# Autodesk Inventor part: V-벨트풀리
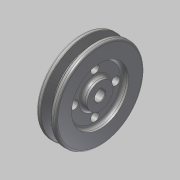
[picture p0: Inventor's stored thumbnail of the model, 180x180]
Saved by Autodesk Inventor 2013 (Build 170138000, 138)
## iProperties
Created: 2015-09
Part Number: V-벨트풀리
Material: 강철, 연강
Document SubType Name: Modeling
Designer: mduedu
Density: 1 g/cm^3
Author: mduedu
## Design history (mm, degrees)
sketch "스케치1"
  geometry: L1 (-9.5, 0)-(9.5, 0); L2 (-9.5, 0)-(-9.5, 42.7); L3 (-9.5, 42.7)-(-4.877, 42.7); L4 (-4.877, 42.7)-(-1.953, 33.7); L5 (-1.953, 33.7)-(1.953, 33.7); L6 (1.953, 33.7)-(4.877, 42.7); L7 (4.877, 42.7)-(9.5, 42.7); L8 (9.5, 42.7)-(9.5, 0); L9 (0, 0)-(0, 33.7); L10 (-9.5, 40)-(9.5, 40); 3 further points
  constraints: 20 end point, 6 point on line, 3 perpendicular, 2 midpoint, 2 parallel, 2 symmetric about line, 1 coincident, 1 collinear, 1 equal length, 1 horizontal, 1 vertical, 1 vertical alignment
  dimensions: "d0" = 19 distance between parallel lines of L8 L2; "d5" = 6.3 distance between parallel lines of L5 L10; "d6" = 8 distance of point (4, 40) point (-4, 40); "d7" = 36 deg angle of L6 L4; "d40" = 2.7 distance between parallel lines of L10 L3; "d82" = 80 diameter of L10 L1; "d83" = 85.4 diameter of L3 L1 (derived)
revolve "회전1" sketch "스케치1" stored, may be unused: angle "d8" = 90 deg
sketch "스케치2"
  geometry: C1 r 12.5 at (0, 0); C2 r 27.5 at (0, 0); 1 further point
  constraints: 2 centre point, 2 coincident
  dimensions: "d9" = 25 diameter of C1; "d41" = 55 diameter of C2
extrude "돌출5" cut sketch "스케치2" distance "d42" = 5; taper "d43" = 0 deg
hole "구멍2" diameter "d46" = 10; stored, may be unused: countersink angle "d50" = 90 deg, drill point angle "d52" = 118 deg; dims "d47" = 6, "d48" = 4, "d49" = 2, "d51" = 8, "d84" = 10, "d85" = 10
sketch "스케치8"
  geometry: L1 (-1.5, 4.77)-(1.5, 4.77); L2 (1.5, 4.77)-(1.5, 6.4); L3 (1.5, 6.4)-(-1.5, 6.4); L4 (-1.5, 6.4)-(-1.5, 4.77); A1 r 5 centre (0, 0) between (-1.5, 4.77) and (1.5, 4.77) reference; 1 further point
  constraints: 8 end point, 2 parallel, 2 point on circle, 1 horizontal, 1 perpendicular
  dimensions: "d53" = 3 distance of L2.end L3.end; "d55" = 11.4 dimension on A1 L3
extrude "돌출6" cut sketch "스케치8" stored distance "d56" = 5; taper "d57" = 0 deg
fillet "모깎기5" dims "d71" = 2, "d72" = 1, "d73" = 0.5
fillet "모깎기7" dims "d75" = 3
fillet "모깎기8" dims "d76" = 3
sketch "스케치10"
  geometry: C1 r 35 at (0, 0); 1 further point
  constraints: 1 centre point, 1 coincident, 1 other
  dimensions: "d77" = 70 diameter of C1
extrude "돌출8" join sketch "스케치10" distance "d80" = 0.5; taper "d81" = 0 deg
chamfer "모따기4" distance "d88" = 0.5; stored, may be unused: second distance "d89" = 2, angle "d90" = 45 deg
sketch "스케치11" dims "d91" = 40
  geometry: C1 r 4 at (0, 20); 2 further points
  constraints: 2 vertical alignment, 1 centre point, 1 coincident, 2 other
  dimensions: "d92" = 8 diameter of C1
extrude "돌출9" cut sketch "스케치11" stored distance "d93" = 10; taper "d94" = 0 deg
node "솔리드1"
mirror "대칭2"
pattern_circular "원형 패턴2" dims angle "d96" = 360 deg
